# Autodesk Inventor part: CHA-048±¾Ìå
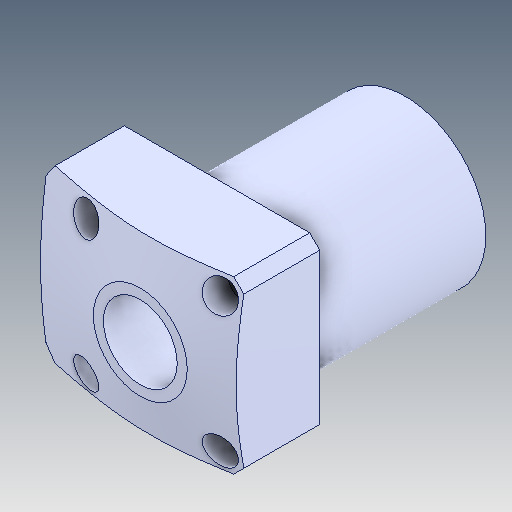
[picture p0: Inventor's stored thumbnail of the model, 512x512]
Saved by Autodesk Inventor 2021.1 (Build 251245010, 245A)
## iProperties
Created: 2021-05
Part Number: CHA-048±¾Ìå
Material: Ogólny
Document SubType Name: Modeling
Designer: user
Density: 1 g/cm^3
Appearance: Domyślna
Author: user
Revision Number: ÈÎºÎ
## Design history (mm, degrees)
feature "µ¹½Ç1"
node "Bryła1"
